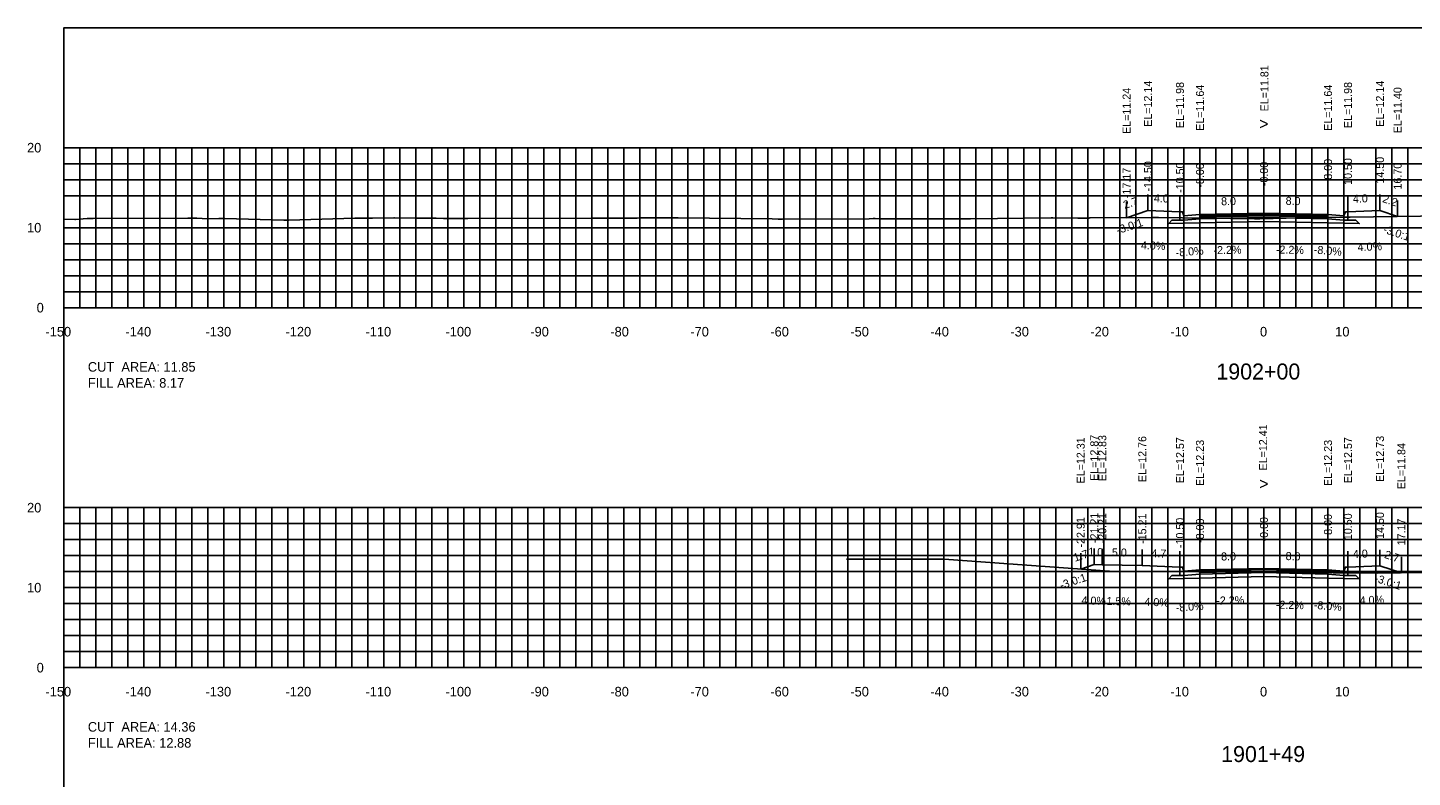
# Model space of a CAD drawing. Extents: x 1800768 to 1802445, y 250079 to 250269.
# Drawn here: x 1802136.5 to 1802309.5, y 250175.7 to 250269.4 of the extents above; entities that cross this region are included whole.
import ezdxf

# ---------------------------------------------------------------- set-up
doc = ezdxf.new("R2010")
doc.units = 0
for name, color, linetype in [('1', 7, 'Continuous'), ('10', 7, 'Continuous'), ('3', 7, 'Continuous'), ('31', 7, 'Continuous'), ('4', 7, 'Continuous'), ('60', 7, 'Continuous'), ('ANNO-TXT', 7, 'Continuous'), ('BASE', 7, 'Continuous'), ('CL-CNST', 7, 'Continuous'), ('Level 62', 7, 'Continuous'), ('LOWER BINDER', 7, 'Continuous'), ('M-ROADS', 7, 'Continuous'), ('UPPER BINDER', 7, 'Continuous'), ('WEARING', 7, 'Continuous')]:
    doc.layers.add(name, color=color, linetype=linetype)

msp = doc.modelspace()

# ---------------------------------------------------------------- linework, layer by layer
for p, q in [((1802273.83, 250245.68), (1802273.83, 250247.68)), ((1802276.5, 250246.57), (1802276.5, 250248.57)), ((1802280.5, 250246.41), (1802280.5, 250248.41)), ((1802283, 250246.07), (1802283, 250248.07)), ((1802291, 250246.24), (1802291, 250248.24)), ((1802299, 250246.07), (1802299, 250248.07)), ((1802301.5, 250246.41), (1802301.5, 250248.41)), ((1802305.5, 250246.57), (1802305.5, 250248.57)), ((1802307.7, 250245.83), (1802307.7, 250247.83)), ((1802268.09, 250201.74), (1802268.09, 250203.74)), ((1802269.79, 250202.31), (1802269.79, 250204.31)), ((1802270.79, 250202.27), (1802270.79, 250204.27)), ((1802275.79, 250202.19), (1802275.79, 250204.19)), ((1802280.5, 250202), (1802280.5, 250204)), ((1802283, 250201.66), (1802283, 250203.66)), ((1802291, 250201.84), (1802291, 250203.84)), ((1802299, 250201.66), (1802299, 250203.66)), ((1802301.5, 250202), (1802301.5, 250204)), ((1802305.5, 250202.16), (1802305.5, 250204.16)), ((1802308.17, 250201.27), (1802308.17, 250203.27))]:
    msp.add_line(p, q)
for points in [[(1802141, 250079.43), (1802441, 250079.43), (1802441, 250269.43), (1802141, 250269.43)], [(1802283, 250246.07), (1802281, 250245.91), (1802280.83, 250246.41), (1802280.5, 250246.41), (1802280.5, 250245.38), (1802281, 250245.38), (1802283, 250245.54)], [(1802299, 250246.07), (1802301, 250245.91), (1802301.17, 250246.41), (1802301.5, 250246.41), (1802301.5, 250245.38), (1802301, 250245.38), (1802299, 250245.54)], [(1802283, 250201.66), (1802281, 250201.5), (1802280.83, 250202), (1802280.5, 250202), (1802280.5, 250200.97), (1802281, 250200.97), (1802283, 250201.13)], [(1802299, 250201.66), (1802301, 250201.5), (1802301.17, 250202), (1802301.5, 250202), (1802301.5, 250200.97), (1802301, 250200.97), (1802299, 250201.13)]]:
    msp.add_lwpolyline(points, close=True)
at = {"layer": '60'}
for p, q in [((1802140.94, 250254.43), (1802141, 250254.43)), ((1802141, 250234.43), (1802141, 250254.43)), ((1802140.94, 250244.43), (1802141, 250244.43)), ((1802140.94, 250234.43), (1802141, 250234.43)), ((1802141, 250234.43), (1802441, 250234.43)), ((1802141, 250234.37), (1802141, 250234.43)), ((1802151, 250234.37), (1802151, 250234.43)), ((1802161, 250234.37), (1802161, 250234.43)), ((1802171, 250234.37), (1802171, 250234.43)), ((1802181, 250234.37), (1802181, 250234.43)), ((1802191, 250234.37), (1802191, 250234.43)), ((1802201, 250234.37), (1802201, 250234.43)), ((1802211, 250234.37), (1802211, 250234.43)), ((1802221, 250234.37), (1802221, 250234.43)), ((1802231, 250234.37), (1802231, 250234.43)), ((1802241, 250234.37), (1802241, 250234.43)), ((1802251, 250234.37), (1802251, 250234.43)), ((1802261, 250234.37), (1802261, 250234.43)), ((1802271, 250234.37), (1802271, 250234.43)), ((1802281, 250234.37), (1802281, 250234.43)), ((1802291, 250234.37), (1802291, 250234.43)), ((1802301, 250234.37), (1802301, 250234.43)), ((1802140.94, 250209.43), (1802141, 250209.43)), ((1802141, 250189.43), (1802141, 250209.43)), ((1802140.94, 250199.43), (1802141, 250199.43)), ((1802140.94, 250189.43), (1802141, 250189.43)), ((1802141, 250189.43), (1802441, 250189.43)), ((1802141, 250189.37), (1802141, 250189.43)), ((1802151, 250189.37), (1802151, 250189.43)), ((1802161, 250189.37), (1802161, 250189.43)), ((1802171, 250189.37), (1802171, 250189.43)), ((1802181, 250189.37), (1802181, 250189.43)), ((1802191, 250189.37), (1802191, 250189.43)), ((1802201, 250189.37), (1802201, 250189.43)), ((1802211, 250189.37), (1802211, 250189.43)), ((1802221, 250189.37), (1802221, 250189.43)), ((1802231, 250189.37), (1802231, 250189.43)), ((1802241, 250189.37), (1802241, 250189.43)), ((1802251, 250189.37), (1802251, 250189.43)), ((1802261, 250189.37), (1802261, 250189.43)), ((1802271, 250189.37), (1802271, 250189.43)), ((1802281, 250189.37), (1802281, 250189.43)), ((1802291, 250189.37), (1802291, 250189.43)), ((1802301, 250189.37), (1802301, 250189.43))]:
    msp.add_line(p, q, dxfattribs=at)
at = {"layer": 'BASE'}
for points in [[(1802299, 250245.04), (1802302.9, 250244.95), (1802302.5, 250245.36), (1802301.5, 250245.38), (1802301, 250245.38), (1802299, 250245.54), (1802291, 250245.71), (1802283, 250245.54), (1802281, 250245.38), (1802280.5, 250245.38), (1802279.5, 250245.36), (1802279.1, 250244.95), (1802283, 250245.04), (1802291, 250245.21)], [(1802299, 250200.63), (1802302.9, 250200.55), (1802302.5, 250200.95), (1802301.5, 250200.97), (1802301, 250200.97), (1802299, 250201.13), (1802291, 250201.31), (1802283, 250201.13), (1802281, 250200.97), (1802280.5, 250200.97), (1802279.5, 250200.95), (1802279.1, 250200.55), (1802283, 250200.63), (1802291, 250200.81)]]:
    msp.add_lwpolyline(points, close=True, dxfattribs=at)
at = {"layer": 'CL-CNST'}
for points in [[(1802273.83, 250245.68), (1802276.5, 250246.57), (1802280.5, 250246.41), (1802280.83, 250246.41), (1802281, 250245.91), (1802283, 250246.07), (1802291, 250246.24), (1802299, 250246.07), (1802301, 250245.91), (1802301.17, 250246.41), (1802301.5, 250246.41), (1802305.5, 250246.57), (1802307.7, 250245.83)], [(1802268.09, 250201.74), (1802269.79, 250202.31), (1802270.79, 250202.27), (1802275.79, 250202.19), (1802280.5, 250202), (1802280.83, 250202), (1802281, 250201.5), (1802283, 250201.66), (1802291, 250201.84), (1802299, 250201.66), (1802301, 250201.5), (1802301.17, 250202), (1802301.5, 250202), (1802305.5, 250202.16), (1802308.17, 250201.27)]]:
    msp.add_lwpolyline(points, dxfattribs=at)
at = {"layer": 'Level 62'}
for p, q in [((1802141, 250254.43), (1802441, 250254.43)), ((1802141, 250234.43), (1802141, 250254.43)), ((1802143, 250234.43), (1802143, 250254.43)), ((1802145, 250234.43), (1802145, 250254.43)), ((1802147, 250234.43), (1802147, 250254.43)), ((1802149, 250234.43), (1802149, 250254.43)), ((1802151, 250234.43), (1802151, 250254.43)), ((1802153, 250234.43), (1802153, 250254.43)), ((1802155, 250234.43), (1802155, 250254.43)), ((1802157, 250234.43), (1802157, 250254.43)), ((1802159, 250234.43), (1802159, 250254.43)), ((1802161, 250234.43), (1802161, 250254.43)), ((1802163, 250234.43), (1802163, 250254.43)), ((1802165, 250234.43), (1802165, 250254.43)), ((1802167, 250234.43), (1802167, 250254.43)), ((1802169, 250234.43), (1802169, 250254.43)), ((1802171, 250234.43), (1802171, 250254.43)), ((1802173, 250234.43), (1802173, 250254.43)), ((1802175, 250234.43), (1802175, 250254.43)), ((1802177, 250234.43), (1802177, 250254.43)), ((1802179, 250234.43), (1802179, 250254.43)), ((1802181, 250234.43), (1802181, 250254.43)), ((1802183, 250234.43), (1802183, 250254.43)), ((1802185, 250234.43), (1802185, 250254.43)), ((1802187, 250234.43), (1802187, 250254.43)), ((1802189, 250234.43), (1802189, 250254.43)), ((1802191, 250234.43), (1802191, 250254.43)), ((1802193, 250234.43), (1802193, 250254.43)), ((1802195, 250234.43), (1802195, 250254.43)), ((1802197, 250234.43), (1802197, 250254.43)), ((1802199, 250234.43), (1802199, 250254.43)), ((1802201, 250234.43), (1802201, 250254.43)), ((1802203, 250234.43), (1802203, 250254.43)), ((1802205, 250234.43), (1802205, 250254.43)), ((1802207, 250234.43), (1802207, 250254.43)), ((1802209, 250234.43), (1802209, 250254.43)), ((1802211, 250234.43), (1802211, 250254.43)), ((1802213, 250234.43), (1802213, 250254.43)), ((1802215, 250234.43), (1802215, 250254.43)), ((1802217, 250234.43), (1802217, 250254.43)), ((1802219, 250234.43), (1802219, 250254.43)), ((1802221, 250234.43), (1802221, 250254.43)), ((1802223, 250234.43), (1802223, 250254.43)), ((1802225, 250234.43), (1802225, 250254.43)), ((1802227, 250234.43), (1802227, 250254.43)), ((1802229, 250234.43), (1802229, 250254.43)), ((1802231, 250234.43), (1802231, 250254.43)), ((1802233, 250234.43), (1802233, 250254.43)), ((1802235, 250234.43), (1802235, 250254.43)), ((1802237, 250234.43), (1802237, 250254.43)), ((1802239, 250234.43), (1802239, 250254.43)), ((1802241, 250234.43), (1802241, 250254.43)), ((1802243, 250234.43), (1802243, 250254.43)), ((1802245, 250234.43), (1802245, 250254.43)), ((1802247, 250234.43), (1802247, 250254.43)), ((1802249, 250234.43), (1802249, 250254.43)), ((1802251, 250234.43), (1802251, 250254.43)), ((1802253, 250234.43), (1802253, 250254.43)), ((1802255, 250234.43), (1802255, 250254.43)), ((1802257, 250234.43), (1802257, 250254.43)), ((1802259, 250234.43), (1802259, 250254.43)), ((1802261, 250234.43), (1802261, 250254.43)), ((1802263, 250234.43), (1802263, 250254.43)), ((1802265, 250234.43), (1802265, 250254.43)), ((1802267, 250234.43), (1802267, 250254.43)), ((1802269, 250234.43), (1802269, 250254.43)), ((1802271, 250234.43), (1802271, 250254.43)), ((1802273, 250234.43), (1802273, 250254.43)), ((1802275, 250234.43), (1802275, 250254.43)), ((1802277, 250234.43), (1802277, 250254.43)), ((1802279, 250234.43), (1802279, 250254.43)), ((1802281, 250234.43), (1802281, 250254.43)), ((1802283, 250234.43), (1802283, 250254.43)), ((1802285, 250234.43), (1802285, 250254.43)), ((1802287, 250234.43), (1802287, 250254.43)), ((1802289, 250234.43), (1802289, 250254.43)), ((1802291, 250234.43), (1802291, 250254.43)), ((1802293, 250234.43), (1802293, 250254.43)), ((1802295, 250234.43), (1802295, 250254.43)), ((1802297, 250234.43), (1802297, 250254.43)), ((1802299, 250234.43), (1802299, 250254.43)), ((1802301, 250234.43), (1802301, 250254.43)), ((1802305, 250234.43), (1802305, 250254.43)), ((1802307, 250234.43), (1802307, 250254.43)), ((1802309, 250234.43), (1802309, 250254.43)), ((1802141, 250252.43), (1802441, 250252.43)), ((1802141, 250250.43), (1802441, 250250.43)), ((1802141, 250248.43), (1802441, 250248.43)), ((1802141, 250244.43), (1802441, 250244.43)), ((1802141, 250242.43), (1802441, 250242.43)), ((1802141, 250240.43), (1802441, 250240.43)), ((1802141, 250238.43), (1802441, 250238.43)), ((1802141, 250236.43), (1802441, 250236.43)), ((1802141, 250234.43), (1802441, 250234.43)), ((1802141, 250209.43), (1802441, 250209.43)), ((1802141, 250189.43), (1802141, 250209.43)), ((1802143, 250189.43), (1802143, 250209.43)), ((1802145, 250189.43), (1802145, 250209.43)), ((1802147, 250189.43), (1802147, 250209.43)), ((1802149, 250189.43), (1802149, 250209.43)), ((1802151, 250189.43), (1802151, 250209.43)), ((1802153, 250189.43), (1802153, 250209.43)), ((1802155, 250189.43), (1802155, 250209.43)), ((1802157, 250189.43), (1802157, 250209.43)), ((1802159, 250189.43), (1802159, 250209.43)), ((1802161, 250189.43), (1802161, 250209.43)), ((1802163, 250189.43), (1802163, 250209.43)), ((1802165, 250189.43), (1802165, 250209.43)), ((1802167, 250189.43), (1802167, 250209.43)), ((1802169, 250189.43), (1802169, 250209.43)), ((1802171, 250189.43), (1802171, 250209.43)), ((1802173, 250189.43), (1802173, 250209.43)), ((1802175, 250189.43), (1802175, 250209.43)), ((1802177, 250189.43), (1802177, 250209.43)), ((1802179, 250189.43), (1802179, 250209.43)), ((1802181, 250189.43), (1802181, 250209.43)), ((1802183, 250189.43), (1802183, 250209.43)), ((1802185, 250189.43), (1802185, 250209.43)), ((1802187, 250189.43), (1802187, 250209.43)), ((1802189, 250189.43), (1802189, 250209.43)), ((1802191, 250189.43), (1802191, 250209.43)), ((1802193, 250189.43), (1802193, 250209.43)), ((1802195, 250189.43), (1802195, 250209.43)), ((1802197, 250189.43), (1802197, 250209.43)), ((1802199, 250189.43), (1802199, 250209.43)), ((1802201, 250189.43), (1802201, 250209.43)), ((1802203, 250189.43), (1802203, 250209.43)), ((1802205, 250189.43), (1802205, 250209.43)), ((1802207, 250189.43), (1802207, 250209.43)), ((1802209, 250189.43), (1802209, 250209.43)), ((1802211, 250189.43), (1802211, 250209.43)), ((1802213, 250189.43), (1802213, 250209.43)), ((1802215, 250189.43), (1802215, 250209.43)), ((1802217, 250189.43), (1802217, 250209.43)), ((1802219, 250189.43), (1802219, 250209.43)), ((1802221, 250189.43), (1802221, 250209.43)), ((1802223, 250189.43), (1802223, 250209.43)), ((1802225, 250189.43), (1802225, 250209.43)), ((1802227, 250189.43), (1802227, 250209.43)), ((1802229, 250189.43), (1802229, 250209.43)), ((1802231, 250189.43), (1802231, 250209.43)), ((1802233, 250189.43), (1802233, 250209.43)), ((1802235, 250189.43), (1802235, 250209.43)), ((1802237, 250189.43), (1802237, 250209.43)), ((1802239, 250189.43), (1802239, 250209.43)), ((1802241, 250189.43), (1802241, 250209.43)), ((1802243, 250189.43), (1802243, 250209.43)), ((1802245, 250189.43), (1802245, 250209.43)), ((1802247, 250189.43), (1802247, 250209.43)), ((1802249, 250189.43), (1802249, 250209.43)), ((1802251, 250189.43), (1802251, 250209.43)), ((1802253, 250189.43), (1802253, 250209.43)), ((1802255, 250189.43), (1802255, 250209.43)), ((1802257, 250189.43), (1802257, 250209.43)), ((1802259, 250189.43), (1802259, 250209.43)), ((1802261, 250189.43), (1802261, 250209.43)), ((1802263, 250189.43), (1802263, 250209.43)), ((1802265, 250189.43), (1802265, 250209.43)), ((1802267, 250189.43), (1802267, 250209.43)), ((1802269, 250189.43), (1802269, 250209.43)), ((1802271, 250189.43), (1802271, 250209.43)), ((1802273, 250189.43), (1802273, 250209.43)), ((1802275, 250189.43), (1802275, 250209.43)), ((1802277, 250189.43), (1802277, 250209.43)), ((1802279, 250189.43), (1802279, 250209.43)), ((1802281, 250189.43), (1802281, 250209.43)), ((1802283, 250189.43), (1802283, 250209.43)), ((1802285, 250189.43), (1802285, 250209.43)), ((1802287, 250189.43), (1802287, 250209.43)), ((1802289, 250189.43), (1802289, 250209.43)), ((1802291, 250189.43), (1802291, 250209.43)), ((1802293, 250189.43), (1802293, 250209.43)), ((1802295, 250189.43), (1802295, 250209.43)), ((1802297, 250189.43), (1802297, 250209.43)), ((1802299, 250189.43), (1802299, 250209.43)), ((1802301, 250189.43), (1802301, 250209.43)), ((1802303, 250189.43), (1802303, 250209.43)), ((1802305, 250189.43), (1802305, 250209.43)), ((1802307, 250189.43), (1802307, 250209.43)), ((1802309, 250189.43), (1802309, 250209.43)), ((1802141, 250207.43), (1802441, 250207.43)), ((1802141, 250205.43), (1802441, 250205.43)), ((1802141, 250203.43), (1802441, 250203.43)), ((1802141, 250201.43), (1802441, 250201.43)), ((1802141, 250199.43), (1802441, 250199.43)), ((1802141, 250197.43), (1802441, 250197.43)), ((1802141, 250195.43), (1802441, 250195.43)), ((1802141, 250193.43), (1802441, 250193.43)), ((1802141, 250191.43), (1802441, 250191.43)), ((1802141, 250189.43), (1802441, 250189.43))]:
    msp.add_line(p, q, dxfattribs=at)
at = {"layer": 'LOWER BINDER'}
for points in [[(1802283, 250245.73), (1802291, 250245.9), (1802299, 250245.73), (1802299, 250245.54), (1802291, 250245.71), (1802283, 250245.54)], [(1802283, 250201.13), (1802283, 250201.32), (1802291, 250201.5), (1802299, 250201.32), (1802299, 250201.13), (1802291, 250201.31)]]:
    msp.add_lwpolyline(points, close=True, dxfattribs=at)
at = {"layer": 'M-ROADS'}
for points in [[(1802141, 250245.49), (1802142.39, 250245.45), (1802142.46, 250245.45), (1802143.9, 250245.59), (1802144.33, 250245.59), (1802144.35, 250245.59), (1802144.65, 250245.59), (1802156.49, 250245.64), (1802156.77, 250245.63), (1802156.79, 250245.63), (1802157.06, 250245.63), (1802157.35, 250245.63), (1802157.64, 250245.63), (1802158.94, 250245.54), (1802160.38, 250245.59), (1802160.9, 250245.58), (1802161.11, 250245.58), (1802168.48, 250245.37), (1802168.72, 250245.37), (1802169.11, 250245.37), (1802177.35, 250245.6), (1802178.07, 250245.6), (1802178.18, 250245.61), (1802179.31, 250245.62), (1802179.44, 250245.62), (1802179.57, 250245.62), (1802182.24, 250245.66), (1802182.34, 250245.66), (1802184.92, 250245.64), (1802185.78, 250245.63), (1802186.04, 250245.63), (1802186.78, 250245.62), (1802187.09, 250245.62), (1802187.14, 250245.62), (1802187.16, 250245.62), (1802187.35, 250245.61), (1802187.52, 250245.61), (1802188.44, 250245.59), (1802188.68, 250245.59), (1802188.87, 250245.59), (1802191.09, 250245.57), (1802191.45, 250245.56), (1802191.5, 250245.56), (1802206.95, 250245.64), (1802212.64, 250245.63), (1802212.66, 250245.63), (1802213, 250245.65), (1802215.83, 250245.66), (1802216.56, 250245.66), (1802217.23, 250245.66), (1802217.32, 250245.66), (1802217.48, 250245.66), (1802217.75, 250245.66), (1802217.77, 250245.66), (1802217.79, 250245.66), (1802229.51, 250245.52), (1802229.52, 250245.52), (1802229.54, 250245.52), (1802230.27, 250245.51), (1802230.32, 250245.51), (1802230.81, 250245.51), (1802241.65, 250245.55), (1802242.15, 250245.56), (1802242.16, 250245.56), (1802242.4, 250245.56), (1802243.07, 250245.55), (1802243.1, 250245.55), (1802254.33, 250245.53), (1802264.39, 250245.67), (1802264.63, 250245.67), (1802267.74, 250245.62), (1802267.78, 250245.63), (1802267.9, 250245.63), (1802268.32, 250245.64), (1802268.47, 250245.64), (1802268.5, 250245.64), (1802268.61, 250245.63), (1802268.66, 250245.63), (1802268.79, 250245.63), (1802268.81, 250245.63), (1802268.96, 250245.63), (1802269.09, 250245.63), (1802269.1, 250245.63), (1802269.25, 250245.65), (1802276.91, 250245.69), (1802276.91, 250245.69), (1802276.91, 250245.69), (1802276.92, 250245.69), (1802276.92, 250245.69), (1802277.06, 250245.69), (1802277.32, 250245.69), (1802277.48, 250245.69), (1802277.77, 250245.69), (1802277.8, 250245.69), (1802289.81, 250245.52), (1802290.44, 250245.52), (1802290.47, 250245.52), (1802297.12, 250245.7), (1802297.63, 250245.71), (1802297.82, 250245.71), (1802301.02, 250245.74), (1802301.44, 250245.74), (1802301.59, 250245.74), (1802301.6, 250245.74), (1802301.78, 250245.74), (1802313.5, 250245.93)], [(1802238.82, 250202.99), (1802251.01, 250202.99), (1802271.68, 250201.48), (1802305.25, 250201.23), (1802319.39, 250201.44)]]:
    msp.add_lwpolyline(points, dxfattribs=at)
at = {"layer": 'UPPER BINDER'}
for points in [[(1802283, 250245.92), (1802291, 250246.09), (1802299, 250245.92), (1802299, 250245.73), (1802291, 250245.9), (1802283, 250245.73)], [(1802283, 250201.51), (1802291, 250201.69), (1802299, 250201.51), (1802299, 250201.32), (1802291, 250201.5), (1802283, 250201.32)]]:
    msp.add_lwpolyline(points, close=True, dxfattribs=at)
at = {"layer": 'WEARING'}
for points in [[(1802299, 250245.92), (1802299, 250246.07), (1802291, 250246.24), (1802283, 250246.07), (1802283, 250245.92), (1802291, 250246.09)], [(1802299, 250201.51), (1802299, 250201.66), (1802291, 250201.84), (1802283, 250201.66), (1802283, 250201.51), (1802291, 250201.69)]]:
    msp.add_lwpolyline(points, close=True, dxfattribs=at)

# ---------------------------------------------------------------- texts
for rotation, p in [(18.4349, (1802272.73, 250243.6)), (341.5651, (1802305.81, 250243.83)), (18.4349, (1802265.67, 250199.22)), (341.5651, (1802304.73, 250200.22))]:
    msp.add_text('-3.0:1', height=1, rotation=rotation).set_placement(p)
at = {"layer": '1'}
for s, p in [('1902+00', (1802285.05, 250225.45)), ('1901+49', (1802285.65, 250177.63))]:
    msp.add_text(s, height=2, dxfattribs=at).set_placement(p)
at = {"layer": '10'}
for s, p in [('-150', (1802138.7, 250230.83)), ('-140', (1802148.7, 250230.83)), ('-130', (1802158.7, 250230.83)), ('-120', (1802168.7, 250230.83)), ('-110', (1802178.7, 250230.83)), ('-100', (1802188.7, 250230.83)), ('-90', (1802199.3, 250230.83)), ('-80', (1802209.3, 250230.83)), ('-70', (1802219.3, 250230.83)), ('-60', (1802229.3, 250230.83)), ('-50', (1802239.3, 250230.83)), ('-40', (1802249.3, 250230.83)), ('-30', (1802259.3, 250230.83)), ('-20', (1802269.3, 250230.83)), ('-10', (1802279.3, 250230.83)), ('0', (1802290.5, 250230.83)), ('10', (1802299.9, 250230.83)), ('-150', (1802138.7, 250185.83)), ('-140', (1802148.7, 250185.83)), ('-130', (1802158.7, 250185.83)), ('-120', (1802168.7, 250185.83)), ('-110', (1802178.7, 250185.83)), ('-100', (1802188.7, 250185.83)), ('-90', (1802199.3, 250185.83)), ('-80', (1802209.3, 250185.83)), ('-70', (1802219.3, 250185.83)), ('-60', (1802229.3, 250185.83)), ('-50', (1802239.3, 250185.83)), ('-40', (1802249.3, 250185.83)), ('-30', (1802259.3, 250185.83)), ('-20', (1802269.3, 250185.83)), ('-10', (1802279.3, 250185.83)), ('0', (1802290.5, 250185.83)), ('10', (1802299.9, 250185.83))]:
    msp.add_text(s, height=1.2, dxfattribs=at).set_placement(p)
at = {"layer": '3'}
for s, p in [('EL=11.81', (1802291.56, 250258.97)), ('EL=11.24', (1802274.33, 250256.15)), ('EL=12.14', (1802277, 250257.04)), ('EL=11.98', (1802281, 250256.88)), ('EL=11.64', (1802283.5, 250256.54)), ('EL=11.64', (1802299.5, 250256.54)), ('EL=11.98', (1802302, 250256.88)), ('EL=12.14', (1802306, 250257.04)), ('EL=11.40', (1802308.2, 250256.23)), ('8.00', (1802299.5, 250250.43)), ('10.50', (1802302, 250249.78)), ('14.50', (1802306, 250249.94)), ('-17.17', (1802274.33, 250248.13)), ('-14.50', (1802277, 250248.95)), ('-10.50', (1802281, 250248.79)), ('-8.00', (1802283.5, 250249.44)), ('-0.00', (1802291.5, 250249.62)), ('16.70', (1802308.2, 250249.2)), ('EL=12.87', (1802270.29, 250212.78)), ('EL=12.83', (1802271.29, 250212.74)), ('EL=12.76', (1802276.29, 250212.62)), ('EL=12.41', (1802291.39, 250214.08)), ('EL=12.73', (1802306, 250212.64)), ('EL=12.31', (1802268.59, 250212.46)), ('EL=12.57', (1802281, 250212.48)), ('EL=12.23', (1802283.5, 250212.14)), ('EL=12.23', (1802299.5, 250212.14)), ('EL=12.57', (1802302, 250212.48)), ('EL=11.84', (1802308.67, 250211.74)), ('-22.91', (1802268.59, 250204.45)), ('-21.21', (1802270.29, 250205.01)), ('-20.21', (1802271.29, 250204.97)), ('-15.21', (1802276.29, 250204.9)), ('-10.50', (1802281, 250204.38)), ('-8.00', (1802283.5, 250205.03)), ('-0.00', (1802291.5, 250205.21)), ('8.00', (1802299.5, 250206.03)), ('10.50', (1802302, 250205.37)), ('14.50', (1802306, 250205.53)), ('17.17', (1802308.67, 250204.72))]:
    msp.add_text(s, height=1, rotation=90, dxfattribs=at).set_placement(p)
at = {"layer": '31'}
for s, p in [('20', (1802136.4, 250253.83)), ('10', (1802136.4, 250243.83)), ('0', (1802137.6, 250233.83)), ('20', (1802136.4, 250208.83)), ('10', (1802136.4, 250198.83)), ('0', (1802137.6, 250188.83))]:
    msp.add_text(s, height=1.2, dxfattribs=at).set_placement(p)
at = {"layer": '4'}
for s, rotation, p in [('2.7', 18.4349, (1802273.6, 250246.76)), ('4.0', 357.7094, (1802277.23, 250247.64)), ('8.0', 1.2603, (1802285.65, 250247.23)), ('8.0', 358.7397, (1802293.7, 250247.29)), ('4.0', 2.2906, (1802302.13, 250247.54)), ('2.2', 341.5651, (1802305.73, 250247.65)), ('4.0%', 357.7094, (1802275.61, 250241.76)), ('4.0%', 2.2906, (1802302.72, 250241.5)), ('-8.0%', 4.5739, (1802280, 250240.81)), ('-2.2%', 1.2603, (1802284.7, 250241.11)), ('-2.2%', 358.7397, (1802292.48, 250241.21)), ('-8.0%', 355.4261, (1802297.2, 250241.2)), ('1.0', 357.7094, (1802269.02, 250203.44)), ('1.7', 18.4349, (1802267.38, 250202.66)), ('5.0', 359.1406, (1802271.99, 250203.35)), ('4.7', 357.7094, (1802276.91, 250203.25)), ('8.0', 1.2603, (1802285.65, 250202.82)), ('8.0', 358.7397, (1802293.7, 250202.88)), ('4.0', 2.2906, (1802302.13, 250203.13)), ('2.7', 341.5651, (1802305.97, 250203.17)), ('4.0%', 357.7094, (1802268.18, 250197.37)), ('1.5%', 359.1406, (1802271.31, 250197.26)), ('4.0%', 357.7094, (1802276.04, 250197.18)), ('-8.0%', 4.5739, (1802280, 250196.41)), ('-2.2%', 1.2603, (1802285.05, 250197.31)), ('-2.2%', 358.7397, (1802292.48, 250196.81)), ('-8.0%', 355.4261, (1802297.2, 250196.79)), ('4.0%', 2.2906, (1802302.98, 250197.34))]:
    msp.add_text(s, height=1, rotation=rotation, dxfattribs=at).set_placement(p)
at = {"layer": '60'}
for s, height, p in [('>', 1.5, (1802290.39, 250256.68)), ('-', 0.0001, (1802141, 250234.43)), ('>', 1.5, (1802290.39, 250211.68)), ('-', 0.0001, (1802141, 250189.43))]:
    msp.add_text(s, height=height, dxfattribs=at).set_placement(p)
at = {"layer": 'ANNO-TXT'}
for s, p in [('CUT  AREA: 11.85', (1802144, 250226.43)), ('FILL AREA: 8.17', (1802144, 250224.43)), ('CUT  AREA: 14.36', (1802144, 250181.43)), ('FILL AREA: 12.88', (1802144, 250179.43))]:
    msp.add_text(s, height=1.2, dxfattribs=at).set_placement(p)

doc.saveas('drawing.dxf')
